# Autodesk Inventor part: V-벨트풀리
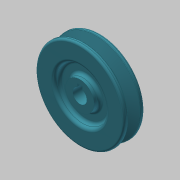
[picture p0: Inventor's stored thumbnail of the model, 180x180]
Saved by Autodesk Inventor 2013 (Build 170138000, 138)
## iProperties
Created: 2019-09
Part Number: V-벨트풀리
Material: 알루미늄 6061
Document SubType Name: Modeling
Designer: mduedu
Density: 1 g/cm^3
Author: mduedu
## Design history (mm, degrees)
sketch "스케치1"
  geometry: L1 (-10, 0)-(10, 0); L2 (10, 0)-(10, 43.5); L3 (10, 43.5)-(-10, 43.5); L4 (-10, 43.5)-(-10, 0); L5 (0, 0)-(0, 43.5); L6 (-5.976, 43.5)-(-2.154, 31); L7 (-2.154, 31)-(2.154, 31); L8 (2.154, 31)-(5.976, 43.5); L9 (-10, 39)-(10, 39); 3 further points
  constraints: 18 end point, 8 point on line, 3 perpendicular, 2 midpoint, 2 parallel, 1 coincident, 1 horizontal, 1 other
  dimensions: "d0" = 87 diameter of L3 L1; "d3" = 12.5 distance between parallel lines of L7 L3; "d4" = 34 deg angle of L8 L6; "d5" = 20 distance between parallel lines of L2 L4; "d6" = 8 distance between parallel lines of L9 L7; "d7" = 9.2 distance of point (4.6, 39) point (-4.6, 39)
revolve "회전1" sketch "스케치1" stored, may be unused: angle "d8" = 90 deg
sketch "스케치2"
  geometry: C1 r 14 at (0, 0); C2 r 25 at (0, 0); 1 further point
  constraints: 2 centre point, 2 coincident
  dimensions: "d9" = 28 diameter of C1; "d10" = 50 diameter of C2
extrude "돌출1" cut sketch "스케치2" distance "d11" = 6; taper "d12" = 0 deg
fillet "모깎기1" dims "d13" = 3
fillet "모깎기2" dims "d14" = 3
fillet "모깎기3" dims "d15" = 0.5, "d16" = 1, "d17" = 2
sketch "스케치3"
  geometry: L1 (-2.5, 6.538)-(2.5, 6.538); L2 (2.5, 6.538)-(2.5, 9.3); L3 (2.5, 9.3)-(-2.5, 9.3); L4 (-2.5, 9.3)-(-2.5, 6.538); A1 r 7 centre (0, 0) between (-2.5, 6.538) and (2.5, 6.538); 1 further point
  constraints: 8 end point, 2 parallel, 2 point on circle, 1 centre point, 1 coincident, 1 horizontal, 1 perpendicular
  dimensions: "d18" = 14 diameter of A1; "d20" = 5 distance of L2.end L3.end; "d21" = 16.3 dimension on A1 L3
extrude "돌출2" cut sketch "스케치3" stored distance "d22" = 6; taper "d23" = 0 deg
node "솔리드1"
mirror "대칭1"
